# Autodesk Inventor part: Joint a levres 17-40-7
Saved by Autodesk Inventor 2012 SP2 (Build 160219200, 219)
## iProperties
Created: 2013-04
Part Number: Joint a levres 17-40-7
Material: Default
Document SubType Name: Modeling
Designer: papa
Density: 1 g/cm^3
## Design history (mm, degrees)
node "Joint a levres 17-40-71"
node "Joint a levres 17-40-7"
node "Base1"
